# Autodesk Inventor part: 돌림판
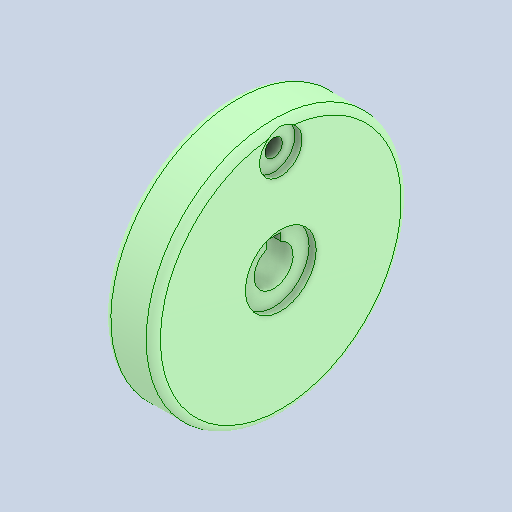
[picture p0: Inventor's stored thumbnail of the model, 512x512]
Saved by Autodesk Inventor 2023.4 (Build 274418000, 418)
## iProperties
Created: 2024-04
Part Number: 돌림판
Material: 일반
Document SubType Name: Modeling
Designer: EDU
Density: 1 g/cm^3
Appearance: 기본값
Author: jhkim
Sending System: Autodesk Inventor 2025
Preprocessor: ST-DEVELOPER v20
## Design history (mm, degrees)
node "돌림판1"
node "솔리드2"
node "솔리드1"
